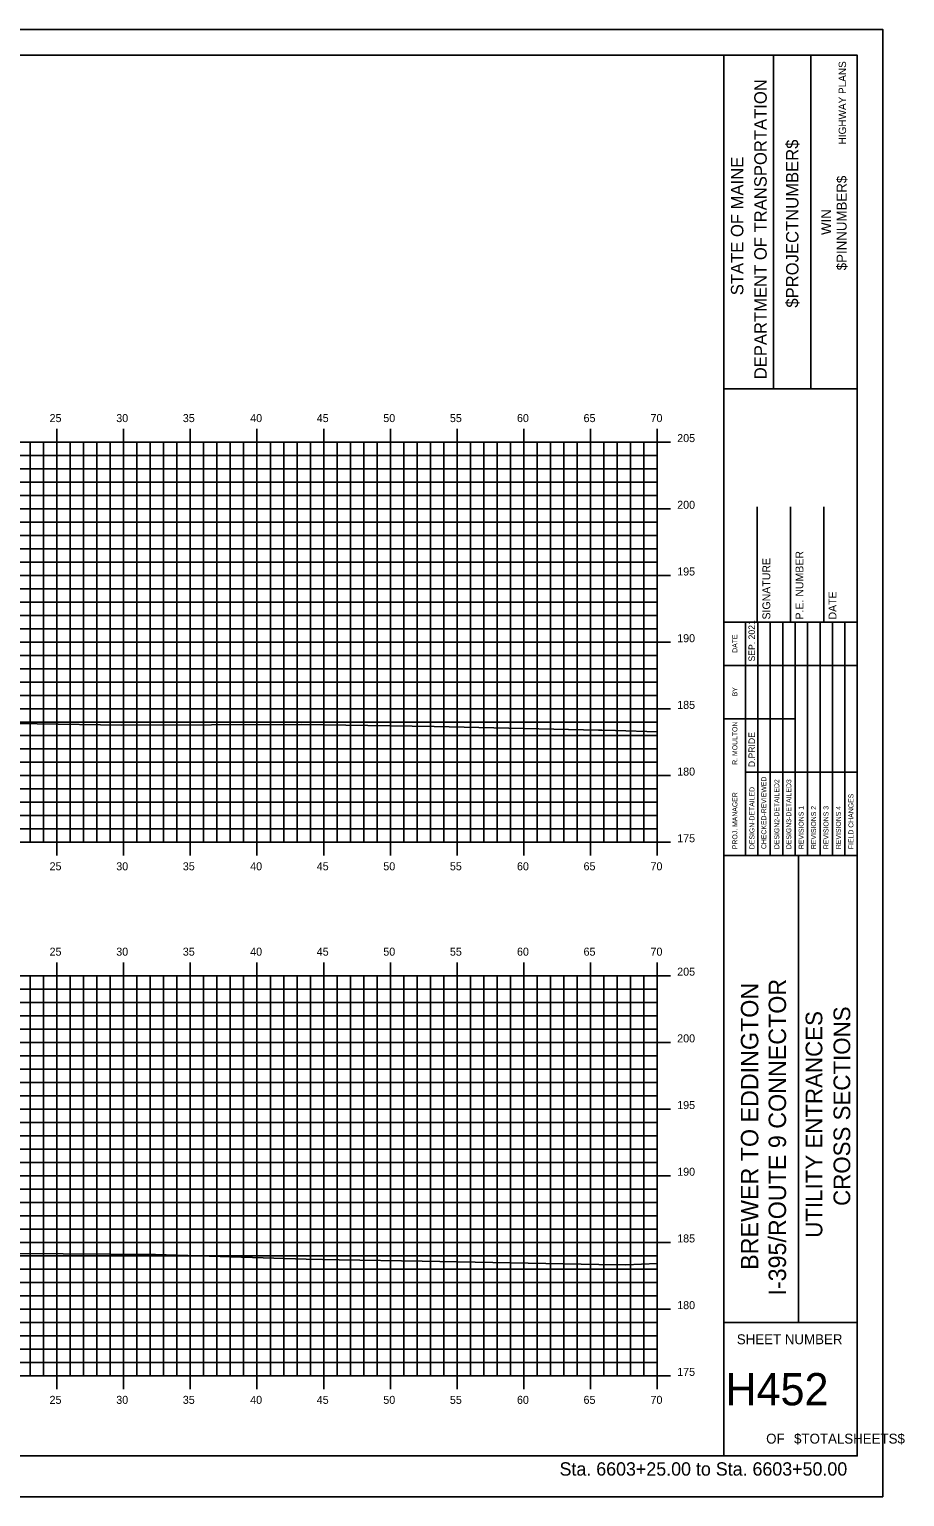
# Model space of a CAD drawing. Extents: x 1724627 to 1724798, y 459560 to 459670.
# Drawn here: x 1724732.7 to 1724798.3, y 459559.6 to 459669.6 of the extents above; entities that cross this region are included whole.
import ezdxf

# ---------------------------------------------------------------- set-up
doc = ezdxf.new("R2010")
doc.units = 0
for name, color, linetype in [('BORDER', 7, 'Continuous'), ('H_V ANNOTATION', 7, 'Continuous'), ('HIGHWAY_TITLE', 7, 'Continuous'), ('MAJOR', 7, 'Continuous'), ('MINOR', 7, 'Continuous'), ('PLOT BOUNDARY', 7, 'Continuous'), ('S_Roadway_Centerline', 7, 'Continuous')]:
    doc.layers.add(name, color=color, linetype=linetype)

msp = doc.modelspace()

# ---------------------------------------------------------------- linework, layer by layer
at = {"layer": 'BORDER'}
for p, q in [((1724784.74, 459562.61), (1724784.74, 459667.61)), ((1724788.47, 459642.61), (1724788.47, 459667.61)), ((1724791.27, 459642.61), (1724791.27, 459667.61)), ((1724784.74, 459642.61), (1724794.74, 459642.61)), ((1724787.24, 459625.12), (1724787.24, 459633.76)), ((1724789.74, 459625.12), (1724789.74, 459633.76)), ((1724792.24, 459625.12), (1724792.24, 459633.76)), ((1724784.74, 459625.12), (1724794.74, 459625.12)), ((1724784.74, 459607.62), (1724794.74, 459607.62)), ((1724790.33, 459572.62), (1724790.33, 459607.62)), ((1724784.74, 459572.62), (1724794.74, 459572.62))]:
    msp.add_line(p, q, dxfattribs=at)
msp.add_lwpolyline([(1724634.74, 459562.61), (1724794.74, 459562.61), (1724794.74, 459667.61), (1724634.74, 459667.61)], close=True, dxfattribs=at)
for points in [[(1724786.36, 459621.87), (1724786.36, 459625.12)], [(1724787.29, 459607.62), (1724787.29, 459625.12)], [(1724788.22, 459625.12), (1724788.22, 459607.62)], [(1724789.15, 459607.62), (1724789.15, 459625.12)], [(1724790.09, 459607.62), (1724790.09, 459625.12)], [(1724791.02, 459607.62), (1724791.02, 459625.12)], [(1724791.95, 459607.62), (1724791.95, 459625.12)], [(1724792.88, 459607.62), (1724792.88, 459625.12)], [(1724793.81, 459607.62), (1724793.81, 459625.12)], [(1724786.36, 459607.62), (1724786.36, 459624.41)], [(1724784.74, 459621.87), (1724794.74, 459621.87)], [(1724784.74, 459617.87), (1724786.36, 459617.87)], [(1724786.36, 459617.87), (1724790.08, 459617.87)], [(1724786.36, 459613.87), (1724794.74, 459613.87)]]:
    msp.add_lwpolyline(points, dxfattribs=at)
at = {"layer": 'MAJOR'}
for p, q in [((1724734.74, 459639.61), (1724734.74, 459638.61)), ((1724739.74, 459639.61), (1724739.74, 459638.61)), ((1724744.74, 459639.61), (1724744.74, 459638.61)), ((1724749.74, 459639.61), (1724749.74, 459638.61)), ((1724754.74, 459639.61), (1724754.74, 459638.61)), ((1724759.74, 459639.61), (1724759.74, 459638.61)), ((1724764.74, 459639.61), (1724764.74, 459638.61)), ((1724769.74, 459639.61), (1724769.74, 459638.61)), ((1724774.74, 459639.61), (1724774.74, 459638.61)), ((1724779.74, 459639.61), (1724779.74, 459638.61)), ((1724639.74, 459638.61), (1724779.74, 459638.61)), ((1724639.74, 459638.61), (1724779.74, 459638.61)), ((1724734.74, 459608.61), (1724734.74, 459638.61)), ((1724739.74, 459608.61), (1724739.74, 459638.61)), ((1724744.74, 459608.61), (1724744.74, 459638.61)), ((1724749.74, 459608.61), (1724749.74, 459638.61)), ((1724754.74, 459608.61), (1724754.74, 459638.61)), ((1724759.74, 459608.61), (1724759.74, 459638.61)), ((1724764.74, 459608.61), (1724764.74, 459638.61)), ((1724769.74, 459608.61), (1724769.74, 459638.61)), ((1724774.74, 459608.61), (1724774.74, 459638.61)), ((1724780.74, 459638.61), (1724778.74, 459638.61)), ((1724779.74, 459608.61), (1724779.74, 459638.61)), ((1724779.74, 459608.61), (1724779.74, 459638.61)), ((1724639.74, 459633.61), (1724779.74, 459633.61)), ((1724780.74, 459633.61), (1724778.74, 459633.61)), ((1724639.74, 459628.61), (1724779.74, 459628.61)), ((1724780.74, 459628.61), (1724778.74, 459628.61)), ((1724639.74, 459623.61), (1724779.74, 459623.61)), ((1724780.74, 459623.61), (1724778.74, 459623.61)), ((1724639.74, 459618.61), (1724779.74, 459618.61)), ((1724780.74, 459618.61), (1724778.74, 459618.61)), ((1724639.74, 459613.61), (1724779.74, 459613.61)), ((1724780.74, 459613.61), (1724778.74, 459613.61)), ((1724639.74, 459608.61), (1724779.74, 459608.61)), ((1724639.74, 459608.61), (1724779.74, 459608.61)), ((1724734.74, 459607.61), (1724734.74, 459608.61)), ((1724739.74, 459607.61), (1724739.74, 459608.61)), ((1724744.74, 459607.61), (1724744.74, 459608.61)), ((1724749.74, 459607.61), (1724749.74, 459608.61)), ((1724754.74, 459607.61), (1724754.74, 459608.61)), ((1724759.74, 459607.61), (1724759.74, 459608.61)), ((1724764.74, 459607.61), (1724764.74, 459608.61)), ((1724769.74, 459607.61), (1724769.74, 459608.61)), ((1724774.74, 459607.61), (1724774.74, 459608.61)), ((1724780.74, 459608.61), (1724778.74, 459608.61)), ((1724779.74, 459607.61), (1724779.74, 459608.61)), ((1724734.74, 459599.61), (1724734.74, 459598.61)), ((1724739.74, 459599.61), (1724739.74, 459598.61)), ((1724744.74, 459599.61), (1724744.74, 459598.61)), ((1724749.74, 459599.61), (1724749.74, 459598.61)), ((1724754.74, 459599.61), (1724754.74, 459598.61)), ((1724759.74, 459599.61), (1724759.74, 459598.61)), ((1724764.74, 459599.61), (1724764.74, 459598.61)), ((1724769.74, 459599.61), (1724769.74, 459598.61)), ((1724774.74, 459599.61), (1724774.74, 459598.61)), ((1724779.74, 459599.61), (1724779.74, 459598.61)), ((1724639.74, 459598.61), (1724779.74, 459598.61)), ((1724639.74, 459598.61), (1724779.74, 459598.61)), ((1724734.74, 459568.61), (1724734.74, 459598.61)), ((1724739.74, 459568.61), (1724739.74, 459598.61)), ((1724744.74, 459568.61), (1724744.74, 459598.61)), ((1724749.74, 459568.61), (1724749.74, 459598.61)), ((1724754.74, 459568.61), (1724754.74, 459598.61)), ((1724759.74, 459568.61), (1724759.74, 459598.61)), ((1724764.74, 459568.61), (1724764.74, 459598.61)), ((1724769.74, 459568.61), (1724769.74, 459598.61)), ((1724774.74, 459568.61), (1724774.74, 459598.61)), ((1724780.74, 459598.61), (1724778.74, 459598.61)), ((1724779.74, 459568.61), (1724779.74, 459598.61)), ((1724779.74, 459568.61), (1724779.74, 459598.61)), ((1724639.74, 459593.61), (1724779.74, 459593.61)), ((1724780.74, 459593.61), (1724778.74, 459593.61)), ((1724639.74, 459588.61), (1724779.74, 459588.61)), ((1724780.74, 459588.61), (1724778.74, 459588.61)), ((1724639.74, 459583.61), (1724779.74, 459583.61)), ((1724780.74, 459583.61), (1724778.74, 459583.61)), ((1724639.74, 459578.61), (1724779.74, 459578.61)), ((1724780.74, 459578.61), (1724778.74, 459578.61)), ((1724639.74, 459573.61), (1724779.74, 459573.61)), ((1724780.74, 459573.61), (1724778.74, 459573.61)), ((1724639.74, 459568.61), (1724779.74, 459568.61)), ((1724639.74, 459568.61), (1724779.74, 459568.61)), ((1724734.74, 459567.61), (1724734.74, 459568.61)), ((1724739.74, 459567.61), (1724739.74, 459568.61)), ((1724744.74, 459567.61), (1724744.74, 459568.61)), ((1724749.74, 459567.61), (1724749.74, 459568.61)), ((1724754.74, 459567.61), (1724754.74, 459568.61)), ((1724759.74, 459567.61), (1724759.74, 459568.61)), ((1724764.74, 459567.61), (1724764.74, 459568.61)), ((1724769.74, 459567.61), (1724769.74, 459568.61)), ((1724774.74, 459567.61), (1724774.74, 459568.61)), ((1724780.74, 459568.61), (1724778.74, 459568.61)), ((1724779.74, 459567.61), (1724779.74, 459568.61))]:
    msp.add_line(p, q, dxfattribs=at)
at = {"layer": 'MINOR'}
for p, q in [((1724732.74, 459608.61), (1724732.74, 459638.61)), ((1724733.74, 459608.61), (1724733.74, 459638.61)), ((1724735.74, 459608.61), (1724735.74, 459638.61)), ((1724736.74, 459608.61), (1724736.74, 459638.61)), ((1724737.74, 459608.61), (1724737.74, 459638.61)), ((1724738.74, 459608.61), (1724738.74, 459638.61)), ((1724740.74, 459608.61), (1724740.74, 459638.61)), ((1724741.74, 459608.61), (1724741.74, 459638.61)), ((1724742.74, 459608.61), (1724742.74, 459638.61)), ((1724743.74, 459608.61), (1724743.74, 459638.61)), ((1724745.74, 459608.61), (1724745.74, 459638.61)), ((1724746.74, 459608.61), (1724746.74, 459638.61)), ((1724747.74, 459608.61), (1724747.74, 459638.61)), ((1724748.74, 459608.61), (1724748.74, 459638.61)), ((1724750.74, 459608.61), (1724750.74, 459638.61)), ((1724751.74, 459608.61), (1724751.74, 459638.61)), ((1724752.74, 459608.61), (1724752.74, 459638.61)), ((1724753.74, 459608.61), (1724753.74, 459638.61)), ((1724755.74, 459608.61), (1724755.74, 459638.61)), ((1724756.74, 459608.61), (1724756.74, 459638.61)), ((1724757.74, 459608.61), (1724757.74, 459638.61)), ((1724758.74, 459608.61), (1724758.74, 459638.61)), ((1724760.74, 459608.61), (1724760.74, 459638.61)), ((1724761.74, 459608.61), (1724761.74, 459638.61)), ((1724762.74, 459608.61), (1724762.74, 459638.61)), ((1724763.74, 459608.61), (1724763.74, 459638.61)), ((1724765.74, 459608.61), (1724765.74, 459638.61)), ((1724766.74, 459608.61), (1724766.74, 459638.61)), ((1724767.74, 459608.61), (1724767.74, 459638.61)), ((1724768.74, 459608.61), (1724768.74, 459638.61)), ((1724770.74, 459608.61), (1724770.74, 459638.61)), ((1724771.74, 459608.61), (1724771.74, 459638.61)), ((1724772.74, 459608.61), (1724772.74, 459638.61)), ((1724773.74, 459608.61), (1724773.74, 459638.61)), ((1724775.74, 459608.61), (1724775.74, 459638.61)), ((1724776.74, 459608.61), (1724776.74, 459638.61)), ((1724777.74, 459608.61), (1724777.74, 459638.61)), ((1724778.74, 459608.61), (1724778.74, 459638.61)), ((1724639.74, 459637.61), (1724779.74, 459637.61)), ((1724779.74, 459637.61), (1724778.74, 459637.61)), ((1724639.74, 459636.61), (1724779.74, 459636.61)), ((1724779.74, 459636.61), (1724778.74, 459636.61)), ((1724639.74, 459635.61), (1724779.74, 459635.61)), ((1724779.74, 459635.61), (1724778.74, 459635.61)), ((1724639.74, 459634.61), (1724779.74, 459634.61)), ((1724779.74, 459634.61), (1724778.74, 459634.61)), ((1724639.74, 459632.61), (1724779.74, 459632.61)), ((1724779.74, 459632.61), (1724778.74, 459632.61)), ((1724639.74, 459631.61), (1724779.74, 459631.61)), ((1724639.74, 459630.61), (1724779.74, 459630.61)), ((1724779.74, 459631.61), (1724778.74, 459631.61)), ((1724779.74, 459630.61), (1724778.74, 459630.61)), ((1724639.74, 459629.61), (1724779.74, 459629.61)), ((1724779.74, 459629.61), (1724778.74, 459629.61)), ((1724639.74, 459627.61), (1724779.74, 459627.61)), ((1724779.74, 459627.61), (1724778.74, 459627.61)), ((1724639.74, 459626.61), (1724779.74, 459626.61)), ((1724779.74, 459626.61), (1724778.74, 459626.61)), ((1724639.74, 459625.61), (1724779.74, 459625.61)), ((1724779.74, 459625.61), (1724778.74, 459625.61)), ((1724639.74, 459624.61), (1724779.74, 459624.61)), ((1724779.74, 459624.61), (1724778.74, 459624.61)), ((1724639.74, 459622.61), (1724779.74, 459622.61)), ((1724779.74, 459622.61), (1724778.74, 459622.61)), ((1724639.74, 459621.61), (1724779.74, 459621.61)), ((1724779.74, 459621.61), (1724778.74, 459621.61)), ((1724639.74, 459620.61), (1724779.74, 459620.61)), ((1724639.74, 459619.61), (1724779.74, 459619.61)), ((1724779.74, 459620.61), (1724778.74, 459620.61)), ((1724779.74, 459619.61), (1724778.74, 459619.61)), ((1724639.74, 459617.61), (1724779.74, 459617.61)), ((1724779.74, 459617.61), (1724778.74, 459617.61)), ((1724639.74, 459616.61), (1724779.74, 459616.61)), ((1724779.74, 459616.61), (1724778.74, 459616.61)), ((1724639.74, 459615.61), (1724779.74, 459615.61)), ((1724779.74, 459615.61), (1724778.74, 459615.61)), ((1724639.74, 459614.61), (1724779.74, 459614.61)), ((1724779.74, 459614.61), (1724778.74, 459614.61)), ((1724639.74, 459612.61), (1724779.74, 459612.61)), ((1724779.74, 459612.61), (1724778.74, 459612.61)), ((1724639.74, 459611.61), (1724779.74, 459611.61)), ((1724779.74, 459611.61), (1724778.74, 459611.61)), ((1724639.74, 459610.61), (1724779.74, 459610.61)), ((1724779.74, 459610.61), (1724778.74, 459610.61)), ((1724639.74, 459609.61), (1724779.74, 459609.61)), ((1724779.74, 459609.61), (1724778.74, 459609.61)), ((1724639.74, 459597.61), (1724779.74, 459597.61)), ((1724732.74, 459568.61), (1724732.74, 459598.61)), ((1724733.74, 459568.61), (1724733.74, 459598.61)), ((1724735.74, 459568.61), (1724735.74, 459598.61)), ((1724736.74, 459568.61), (1724736.74, 459598.61)), ((1724737.74, 459568.61), (1724737.74, 459598.61)), ((1724738.74, 459568.61), (1724738.74, 459598.61)), ((1724740.74, 459568.61), (1724740.74, 459598.61)), ((1724741.74, 459568.61), (1724741.74, 459598.61)), ((1724742.74, 459568.61), (1724742.74, 459598.61)), ((1724743.74, 459568.61), (1724743.74, 459598.61)), ((1724745.74, 459568.61), (1724745.74, 459598.61)), ((1724746.74, 459568.61), (1724746.74, 459598.61)), ((1724747.74, 459568.61), (1724747.74, 459598.61)), ((1724748.74, 459568.61), (1724748.74, 459598.61)), ((1724750.74, 459568.61), (1724750.74, 459598.61)), ((1724751.74, 459568.61), (1724751.74, 459598.61)), ((1724752.74, 459568.61), (1724752.74, 459598.61)), ((1724753.74, 459568.61), (1724753.74, 459598.61)), ((1724755.74, 459568.61), (1724755.74, 459598.61)), ((1724756.74, 459568.61), (1724756.74, 459598.61)), ((1724757.74, 459568.61), (1724757.74, 459598.61)), ((1724758.74, 459568.61), (1724758.74, 459598.61)), ((1724760.74, 459568.61), (1724760.74, 459598.61)), ((1724761.74, 459568.61), (1724761.74, 459598.61)), ((1724762.74, 459568.61), (1724762.74, 459598.61)), ((1724763.74, 459568.61), (1724763.74, 459598.61)), ((1724765.74, 459568.61), (1724765.74, 459598.61)), ((1724766.74, 459568.61), (1724766.74, 459598.61)), ((1724767.74, 459568.61), (1724767.74, 459598.61)), ((1724768.74, 459568.61), (1724768.74, 459598.61)), ((1724770.74, 459568.61), (1724770.74, 459598.61)), ((1724771.74, 459568.61), (1724771.74, 459598.61)), ((1724772.74, 459568.61), (1724772.74, 459598.61)), ((1724773.74, 459568.61), (1724773.74, 459598.61)), ((1724775.74, 459568.61), (1724775.74, 459598.61)), ((1724776.74, 459568.61), (1724776.74, 459598.61)), ((1724777.74, 459568.61), (1724777.74, 459598.61)), ((1724778.74, 459568.61), (1724778.74, 459598.61)), ((1724779.74, 459597.61), (1724778.74, 459597.61)), ((1724639.74, 459596.61), (1724779.74, 459596.61)), ((1724779.74, 459596.61), (1724778.74, 459596.61)), ((1724639.74, 459595.61), (1724779.74, 459595.61)), ((1724779.74, 459595.61), (1724778.74, 459595.61)), ((1724639.74, 459594.61), (1724779.74, 459594.61)), ((1724779.74, 459594.61), (1724778.74, 459594.61)), ((1724639.74, 459592.61), (1724779.74, 459592.61)), ((1724779.74, 459592.61), (1724778.74, 459592.61)), ((1724639.74, 459591.61), (1724779.74, 459591.61)), ((1724779.74, 459591.61), (1724778.74, 459591.61)), ((1724639.74, 459590.61), (1724779.74, 459590.61)), ((1724779.74, 459590.61), (1724778.74, 459590.61)), ((1724639.74, 459589.61), (1724779.74, 459589.61)), ((1724779.74, 459589.61), (1724778.74, 459589.61)), ((1724639.74, 459587.61), (1724779.74, 459587.61)), ((1724639.74, 459586.61), (1724779.74, 459586.61)), ((1724779.74, 459587.61), (1724778.74, 459587.61)), ((1724779.74, 459586.61), (1724778.74, 459586.61)), ((1724639.74, 459585.61), (1724779.74, 459585.61)), ((1724779.74, 459585.61), (1724778.74, 459585.61)), ((1724639.74, 459584.61), (1724779.74, 459584.61)), ((1724779.74, 459584.61), (1724778.74, 459584.61)), ((1724639.74, 459582.61), (1724779.74, 459582.61)), ((1724779.74, 459582.61), (1724778.74, 459582.61)), ((1724639.74, 459581.61), (1724779.74, 459581.61)), ((1724779.74, 459581.61), (1724778.74, 459581.61)), ((1724639.74, 459580.61), (1724779.74, 459580.61)), ((1724779.74, 459580.61), (1724778.74, 459580.61)), ((1724639.74, 459579.61), (1724779.74, 459579.61)), ((1724779.74, 459579.61), (1724778.74, 459579.61)), ((1724639.74, 459577.61), (1724779.74, 459577.61)), ((1724779.74, 459577.61), (1724778.74, 459577.61)), ((1724639.74, 459576.61), (1724779.74, 459576.61)), ((1724639.74, 459575.61), (1724779.74, 459575.61)), ((1724779.74, 459576.61), (1724778.74, 459576.61)), ((1724779.74, 459575.61), (1724778.74, 459575.61)), ((1724639.74, 459574.61), (1724779.74, 459574.61)), ((1724779.74, 459574.61), (1724778.74, 459574.61)), ((1724639.74, 459572.61), (1724779.74, 459572.61)), ((1724779.74, 459572.61), (1724778.74, 459572.61)), ((1724639.74, 459571.61), (1724779.74, 459571.61)), ((1724779.74, 459571.61), (1724778.74, 459571.61)), ((1724639.74, 459570.61), (1724779.74, 459570.61)), ((1724779.74, 459570.61), (1724778.74, 459570.61)), ((1724639.74, 459569.61), (1724779.74, 459569.61)), ((1724779.74, 459569.61), (1724778.74, 459569.61))]:
    msp.add_line(p, q, dxfattribs=at)
at = {"layer": 'PLOT BOUNDARY'}
msp.add_lwpolyline([(1724626.65, 459559.55), (1724796.65, 459559.55), (1724796.65, 459669.55), (1724626.65, 459669.55)], close=True, dxfattribs=at)
at = {"layer": 'S_Roadway_Centerline'}
for points in [[(1724639.74, 459618.64), (1724644.02, 459618.51), (1724646.46, 459618.47), (1724648.51, 459618.41), (1724662.6, 459618.15), (1724669.11, 459618.06), (1724669.94, 459618.04), (1724671.04, 459618.02), (1724690.81, 459618.02), (1724695.78, 459617.95), (1724711.52, 459617.63), (1724715.92, 459617.59), (1724722.15, 459617.58), (1724733.25, 459617.49), (1724739.57, 459617.39), (1724753.07, 459617.44), (1724763.02, 459617.29), (1724775.34, 459617.02), (1724775.49, 459617.02), (1724775.59, 459617.02), (1724776.61, 459616.98), (1724779.74, 459616.89)], [(1724639.74, 459579.05), (1724648.15, 459579), (1724650.09, 459578.95), (1724660.33, 459578.55), (1724669.88, 459578.67), (1724672.27, 459578.67), (1724675.18, 459578.72), (1724690.09, 459578.39), (1724694.55, 459578.21), (1724699.96, 459578.11), (1724703.21, 459578.13), (1724710.28, 459578.02), (1724713.86, 459577.97), (1724726.92, 459577.81), (1724729.62, 459577.8), (1724731.76, 459577.77), (1724742.12, 459577.7), (1724753.42, 459577.35), (1724755.89, 459577.31), (1724762.13, 459577.2), (1724775.36, 459576.96), (1724777.4, 459576.94), (1724779.74, 459577.02)]]:
    msp.add_lwpolyline(points, dxfattribs=at)

# ---------------------------------------------------------------- texts
at = {"layer": 'BORDER'}
for s, height, p in [('DEPARTMENT OF TRANSPORTATION', 0.9318, (1724787.95, 459643.32)), ('$PROJECTNUMBER$', 0.9318, (1724790.33, 459648.69)), ('STATE OF MAINE', 0.9318, (1724786.2, 459649.62)), ('$PINNUMBER$', 0.7453, (1724793.94, 459651.49)), ('WIN', 0.745, (1724792.78, 459654.14)), ('SIGNATURE', 0.591, (1724788.22, 459625.31)), ('P.E. NUMBER', 0.5906, (1724790.7, 459625.31)), ('DATE', 0.591, (1724793.18, 459625.31)), ('SEP. 2021', 0.485, (1724787.07, 459622.16)), ('DATE', 0.371, (1724785.75, 459622.82)), ('BY', 0.371, (1724785.75, 459619.55)), ('R. MOULTON', 0.373, (1724785.75, 459614.42)), ('D.PRIDE', 0.485, (1724787.07, 459614.24)), ('CHECKED-REVIEWED', 0.3727, (1724787.92, 459608.1)), ('DESIGN2-DETAILED2', 0.3727, (1724788.89, 459608.1)), ('DESIGN3-DETAILED3', 0.3727, (1724789.79, 459608.1)), ('PROJ. MANAGER', 0.3727, (1724785.75, 459608.1)), ('DESIGN-DETAILED', 0.3727, (1724787.03, 459608.1)), ('FIELD CHANGES', 0.3727, (1724794.45, 459608.1)), ('REVISIONS 1', 0.3727, (1724790.72, 459608.1)), ('REVISIONS 2', 0.3727, (1724791.65, 459608.1)), ('REVISIONS 3', 0.3727, (1724792.58, 459608.1)), ('REVISIONS 4', 0.3727, (1724793.51, 459608.1)), ('UTILITY ENTRANCES', 1.25, (1724792.12, 459578.96)), ('CROSS SECTIONS', 1.25, (1724794.21, 459581.35))]:
    msp.add_text(s, height=height, rotation=90, dxfattribs=at).set_placement(p)
for s, height, p in [('SHEET NUMBER', 0.7453, (1724785.71, 459570.98)), ('H452', 2.419, (1724784.85, 459566.4)), ('OF', 0.745, (1724787.91, 459563.53)), ('$TOTALSHEETS$', 0.7453, (1724790, 459563.53))]:
    msp.add_text(s, height=height, dxfattribs=at).set_placement(p)
at = {"layer": 'H_V ANNOTATION'}
for s, height, p in [('25', 0.6, (1724734.19, 459640.11)), ('30', 0.6, (1724739.19, 459640.11)), ('35', 0.6, (1724744.18, 459640.11)), ('40', 0.6, (1724749.23, 459640.11)), ('45', 0.6, (1724754.22, 459640.11)), ('50', 0.6, (1724759.21, 459640.11)), ('55', 0.6, (1724764.2, 459640.11)), ('60', 0.6, (1724769.23, 459640.11)), ('65', 0.6, (1724774.22, 459640.11)), ('70', 0.6, (1724779.24, 459640.11)), ('205', 0.6, (1724781.24, 459638.61)), ('200', 0.6, (1724781.24, 459633.61)), ('195', 0.6, (1724781.24, 459628.61)), ('190', 0.6, (1724781.24, 459623.61)), ('185', 0.6, (1724781.24, 459618.61)), ('180', 0.6, (1724781.24, 459613.61)), ('175', 0.6, (1724781.24, 459608.61)), ('25', 0.6, (1724734.19, 459606.51)), ('30', 0.6, (1724739.19, 459606.51)), ('35', 0.6, (1724744.18, 459606.51)), ('40', 0.6, (1724749.23, 459606.51)), ('45', 0.6, (1724754.22, 459606.51)), ('50', 0.6, (1724759.21, 459606.51)), ('55', 0.6, (1724764.2, 459606.51)), ('60', 0.6, (1724769.23, 459606.51)), ('65', 0.6, (1724774.22, 459606.51)), ('70', 0.6, (1724779.24, 459606.51)), ('25', 0.6, (1724734.19, 459600.11)), ('30', 0.6, (1724739.19, 459600.11)), ('35', 0.6, (1724744.18, 459600.11)), ('40', 0.6, (1724749.23, 459600.11)), ('45', 0.6, (1724754.22, 459600.11)), ('50', 0.6, (1724759.21, 459600.11)), ('55', 0.6, (1724764.2, 459600.11)), ('60', 0.6, (1724769.23, 459600.11)), ('65', 0.6, (1724774.22, 459600.11)), ('70', 0.6, (1724779.24, 459600.11)), ('205', 0.6, (1724781.24, 459598.61)), ('200', 0.6, (1724781.24, 459593.61)), ('195', 0.6, (1724781.24, 459588.61)), ('190', 0.6, (1724781.24, 459583.61)), ('185', 0.6, (1724781.24, 459578.61)), ('180', 0.6, (1724781.24, 459573.61)), ('175', 0.6, (1724781.24, 459568.61)), ('25', 0.6, (1724734.19, 459566.51)), ('30', 0.6, (1724739.19, 459566.51)), ('35', 0.6, (1724744.18, 459566.51)), ('40', 0.6, (1724749.23, 459566.51)), ('45', 0.6, (1724754.22, 459566.51)), ('50', 0.6, (1724759.21, 459566.51)), ('55', 0.6, (1724764.2, 459566.51)), ('60', 0.6, (1724769.23, 459566.51)), ('65', 0.6, (1724774.22, 459566.51)), ('70', 0.6, (1724779.24, 459566.51)), ('Sta. 6603+25.00 to Sta. 6603+50.00', 1.0002, (1724772.42, 459561.13))]:
    msp.add_text(s, height=height, dxfattribs=at).set_placement(p)
at = {"layer": 'HIGHWAY_TITLE'}
for s, height, p in [('HIGHWAY PLANS', 0.559, (1724793.9, 459660.93)), ('BREWER TO EDDINGTON', 1.3043, (1724787.32, 459576.56)), ('I-395/ROUTE 9 CONNECTOR', 1.3043, (1724789.4, 459574.63))]:
    msp.add_text(s, height=height, rotation=90, dxfattribs=at).set_placement(p)

doc.saveas('drawing.dxf')
